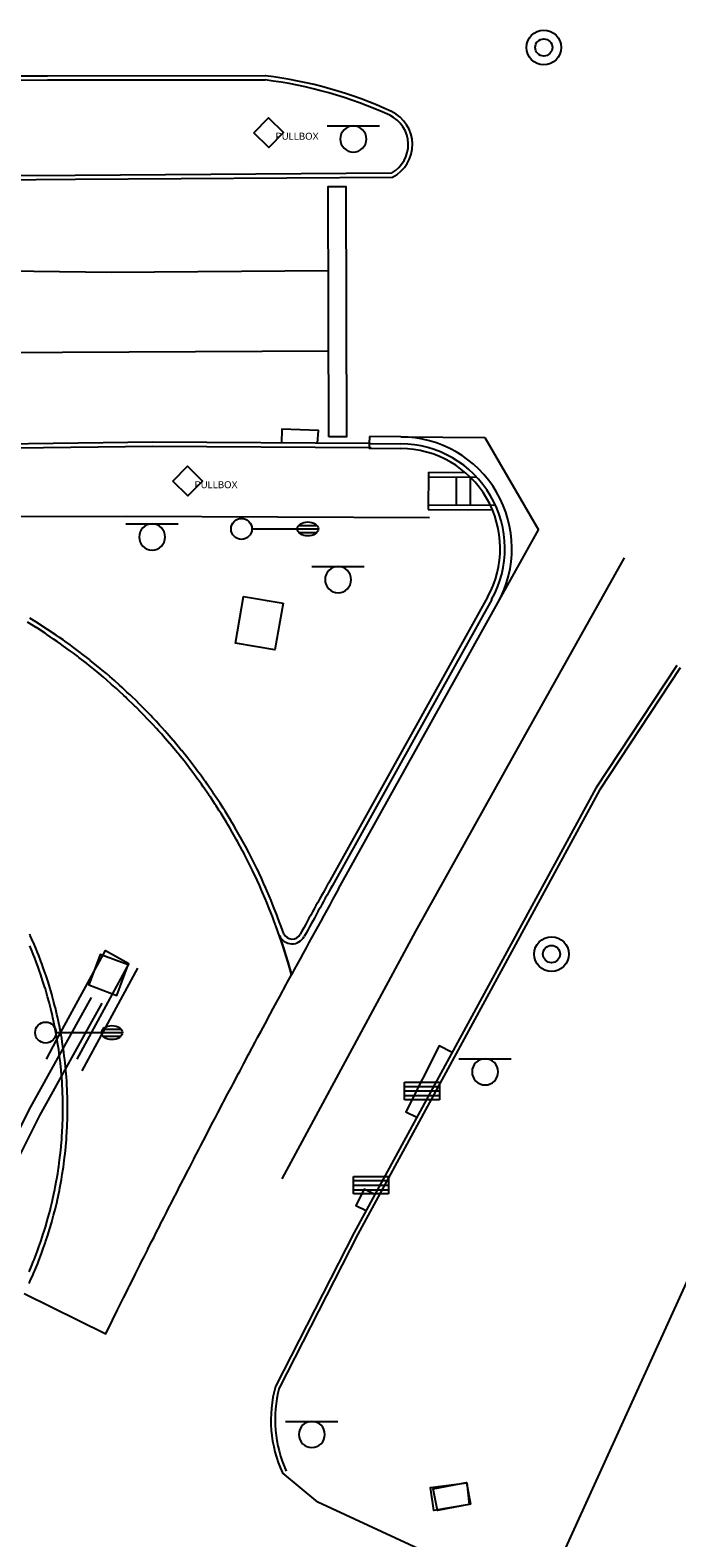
# Model space of a CAD drawing. Extents: x 2145380 to 2157287, y 139568 to 149130.
# Drawn here: x 2151198.1 to 2151290.7, y 148084.3 to 148300.2 of the extents above; entities that cross this region are included whole.
import ezdxf

# ---------------------------------------------------------------- set-up
doc = ezdxf.new("R2010")
doc.units = 0
for name, color, linetype in [('Default', 7, 'Continuous'), ('PR_PREVIOUSLY CONSTRUCTED', 7, 'Continuous'), ('TOPO_Asphalt', 7, 'Continuous'), ('TOPO_Concrete', 7, 'Continuous'), ('TOPO_Curb Back', 7, 'Continuous'), ('TOPO_DRAIN_Inlet Grate', 7, 'Continuous'), ('TOPO_DRAIN_Inlet Top Grate', 7, 'Continuous'), ('TOPO_Flowline', 7, 'Continuous'), ('TOPO_Light Pole', 7, 'Continuous'), ('TOPO_Misc Line', 7, 'Continuous'), ('TOPO_Power Pullbox', 7, 'Continuous'), ('TOPO_San Manhole', 7, 'Continuous'), ('TOPO_Sidewalk', 7, 'Continuous'), ('TOPO_Sign', 7, 'Continuous'), ('TOPO_Wall Freestanding', 7, 'Continuous')]:
    doc.layers.add(name, color=color, linetype=linetype)

# ---------------------------------------------------------------- blocks, each defined once
blk = doc.blocks.new('LP')
at = {"layer": 'TOPO_Light Pole'}
blk.add_line((3.81, 0), (20.32, 0), dxfattribs=at)
for points in [[(20.32, 0), (27.94, 0)], [(20.32, 0), (23.5, 0)], [(20.83, 1.27), (27.43, 1.27)], [(20.83, 1.27), (23.5, 1.27)], [(23.71, 1.27), (27.43, 1.27)], [(23.71, 0), (27.94, 0)], [(20.83, -1.27), (27.43, -1.27)], [(20.83, -1.27), (23.5, -1.27)], [(23.71, -1.27), (27.43, -1.27)]]:
    blk.add_lwpolyline(points, dxfattribs=at)
blk.add_circle((0, 0), 3.81, dxfattribs=at)
blk.add_ellipse((24.13, 0), major_axis=(3.81, 0), ratio=0.666667, dxfattribs=at)
blk = doc.blocks.new('pulbox')
at = {"layer": 'Default'}
blk.add_lwpolyline([(-5.38, -0.01), (-0.02, 5.42), (5.4, 0.06), (0.05, -5.36), (-5.38, -0.01)], dxfattribs=at)
blk.add_text('PULLBOX', height=2.54, dxfattribs=at).set_placement((2.54, -2.54))
blk = doc.blocks.new('EXMHSS')
at = {"layer": 'Default'}
for radius in [6.3, 3.13]:
    blk.add_circle((0, 0), radius, dxfattribs=at)
blk = doc.blocks.new('INLET')
at = {"layer": 'Default'}
for p, q in [((-6.35, 0), (-6.35, 6.35)), ((-6.35, 6.35), (6.35, 6.35)), ((6.35, 6.35), (6.35, 0)), ((-6.35, 4.82), (6.35, 4.82)), ((-6.35, 3.18), (6.35, 3.18)), ((-6.35, 1.47), (6.35, 1.47)), ((6.35, 0), (-6.35, 0))]:
    blk.add_line(p, q, dxfattribs=at)

msp = doc.modelspace()

# ---------------------------------------------------------------- linework, layer by layer
at = {"layer": 'PR_PREVIOUSLY CONSTRUCTED'}
for p, q in [((2151246.7, 148242.01), (2151246.69, 148241.01)), ((2151246.69, 148241.01), (2151251.2, 148240.98)), ((2151251.21, 148241.98), (2151246.7, 148242.01)), ((2151263.21, 148241.9), (2151270.92, 148228.68)), ((2151255.15, 148236.91), (2151255.11, 148231.58)), ((2151255.14, 148236.25), (2151262.08, 148236.2)), ((2151255.15, 148236.91), (2151260.41, 148236.88)), ((2151259.14, 148236.22), (2151259.12, 148232.22)), ((2151261.14, 148236.21), (2151261.12, 148232.21)), ((2151255.12, 148232.25), (2151264.76, 148232.18)), ((2151255.11, 148231.58), (2151264.32, 148231.52)), ((2151263.63, 148219.01), (2151240.83, 148178.05)), ((2151264.21, 148218.68), (2151241.41, 148177.72)), ((2151242.29, 148177.26), (2151265.08, 148218.2))]:
    msp.add_line(p, q, dxfattribs=at)
for points in [[(2151246.69, 148241.01), (2151246.68, 148240.34), (2151251.2, 148240.31)], [(2151251.21, 148241.98), (2151263.21, 148241.9)], [(2151265.08, 148218.2), (2151270.92, 148228.68)], [(2151197.29, 148119.31), (2151208.95, 148113.55), (2151209.49, 148114.64), (2151209.8, 148115.26), (2151210.03, 148115.73), (2151210.57, 148116.83), (2151210.64, 148116.97), (2151211.11, 148117.92), (2151211.49, 148118.68), (2151211.66, 148119.02), (2151212.21, 148120.12), (2151212.35, 148120.4), (2151212.76, 148121.22), (2151213.21, 148122.13), (2151213.31, 148122.33), (2151213.87, 148123.44), (2151214.08, 148123.87), (2151214.43, 148124.55), (2151214.96, 148125.62), (2151214.99, 148125.68), (2151215.56, 148126.81), (2151215.86, 148127.39), (2151216.14, 148127.94), (2151216.72, 148129.09), (2151216.76, 148129.18), (2151217.31, 148130.25), (2151217.69, 148130.99), (2151217.9, 148131.41), (2151218.5, 148132.59), (2151218.62, 148132.83), (2151219.11, 148133.78), (2151219.58, 148134.7), (2151219.72, 148134.98), (2151220.35, 148136.19), (2151220.56, 148136.61), (2151220.98, 148137.42), (2151221.56, 148138.54), (2151221.62, 148138.67), (2151222.28, 148139.93), (2151222.58, 148140.52), (2151222.94, 148141.21), (2151223.61, 148142.51), (2151223.63, 148142.55), (2151224.3, 148143.83), (2151224.72, 148144.62), (2151225, 148145.17), (2151225.72, 148146.54), (2151225.83, 148146.75), (2151226.45, 148147.93), (2151226.98, 148148.95), (2151227.19, 148149.34), (2151227.95, 148150.79), (2151228.18, 148151.2), (2151228.73, 148152.26), (2151229.41, 148153.53), (2151229.53, 148153.76), (2151230.35, 148155.3), (2151230.7, 148155.95), (2151231.19, 148156.87), (2151232.04, 148158.45), (2151232.06, 148158.48), (2151232.94, 148160.14), (2151233.44, 148161.05), (2151233.86, 148161.83), (2151234.8, 148163.57), (2151234.9, 148163.76), (2151235.53, 148164.93), (2151235.53, 148164.93), (2151235.52, 148164.95), (2151235.43, 148165.3), (2151235.15, 148166.31), (2151235, 148166.81), (2151234.55, 148168.31), (2151234.44, 148168.66), (2151234.07, 148169.8), (2151233.66, 148170.98), (2151233.56, 148171.28), (2151233.02, 148172.74), (2151232.82, 148173.28), (2151232.46, 148174.2), (2151231.92, 148175.54), (2151231.87, 148175.64), (2151231.26, 148177.08), (2151230.95, 148177.78), (2151230.62, 148178.5), (2151229.96, 148179.9), (2151229.92, 148179.98), (2151229.27, 148181.29), (2151228.83, 148182.15), (2151228.56, 148182.67), (2151228.54, 148182.71), (2151227.82, 148184.03), (2151227.68, 148184.28), (2151227.64, 148184.35), (2151227.06, 148185.38), (2151226.71, 148185.97), (2151226.47, 148186.38), (2151226.27, 148186.71), (2151225.75, 148187.57), (2151225.47, 148188.03), (2151225.21, 148188.43), (2151224.75, 148189.14), (2151224.64, 148189.32), (2151223.89, 148190.45), (2151223.78, 148190.61), (2151223.73, 148190.69), (2151222.91, 148191.87), (2151222.66, 148192.22), (2151222.52, 148192.42), (2151222.01, 148193.12), (2151221.57, 148193.71), (2151221.1, 148194.35), (2151221.09, 148194.35), (2151220.45, 148195.19), (2151220.16, 148195.56), (2151219.62, 148196.24), (2151219.3, 148196.63), (2151219.2, 148196.75), (2151218.23, 148197.92), (2151218.12, 148198.05), (2151218.09, 148198.08), (2151217.23, 148199.07), (2151216.91, 148199.43), (2151216.52, 148199.87), (2151216.21, 148200.2), (2151215.67, 148200.79), (2151215.18, 148201.32), (2151214.9, 148201.61), (2151214.41, 148202.12), (2151214.13, 148202.41), (2151213.24, 148203.3), (2151213.12, 148203.42), (2151213.06, 148203.48), (2151211.97, 148204.53), (2151211.81, 148204.69), (2151211.54, 148204.94), (2151210.86, 148205.56), (2151210.47, 148205.93), (2151209.79, 148206.53), (2151209.74, 148206.57), (2151209.1, 148207.13), (2151208.61, 148207.56), (2151208.01, 148208.07), (2151207.72, 148208.31), (2151207.46, 148208.53), (2151206.31, 148209.45), (2151206.29, 148209.47), (2151206.19, 148209.55), (2151205.11, 148210.39), (2151204.88, 148210.56), (2151204.33, 148210.98), (2151203.91, 148211.29), (2151203.44, 148211.64), (2151202.71, 148212.16), (2151202.45, 148212.35), (2151201.97, 148212.68), (2151201.49, 148213.02), (2151200.53, 148213.66), (2151200.48, 148213.69), (2151200.25, 148213.85), (2151199.01, 148214.65), (2151198.98, 148214.67), (2151198.58, 148214.92), (2151197.75, 148215.44)], [(2151234.43, 148170.81), (2151234.29, 148171.2), (2151234.19, 148171.5), (2151233.65, 148172.98), (2151233.45, 148173.51), (2151233.08, 148174.45), (2151232.53, 148175.8), (2151232.49, 148175.9), (2151231.87, 148177.34), (2151231.56, 148178.05), (2151231.23, 148178.77), (2151230.56, 148180.19), (2151230.52, 148180.27), (2151229.87, 148181.59), (2151229.42, 148182.46), (2151229.15, 148182.98), (2151229.13, 148183.02), (2151228.4, 148184.35), (2151228.26, 148184.61), (2151228.22, 148184.68), (2151227.64, 148185.71), (2151227.29, 148186.31), (2151227.05, 148186.72), (2151226.85, 148187.05), (2151226.32, 148187.92), (2151226.03, 148188.38), (2151225.77, 148188.79), (2151225.31, 148189.51), (2151225.2, 148189.69), (2151224.44, 148190.82), (2151224.34, 148190.98), (2151224.28, 148191.07), (2151223.46, 148192.25), (2151223.21, 148192.6), (2151223.06, 148192.81), (2151222.55, 148193.51), (2151222.11, 148194.11), (2151221.63, 148194.75), (2151221.62, 148194.76), (2151220.98, 148195.6), (2151220.69, 148195.97), (2151220.14, 148196.66), (2151219.82, 148197.05), (2151219.72, 148197.17), (2151218.73, 148198.35), (2151218.63, 148198.48), (2151218.6, 148198.51), (2151217.73, 148199.51), (2151217.41, 148199.88), (2151217.02, 148200.31), (2151216.71, 148200.66), (2151216.16, 148201.25), (2151215.66, 148201.78), (2151215.39, 148202.07), (2151214.89, 148202.59), (2151214.6, 148202.88), (2151213.71, 148203.77), (2151213.59, 148203.9), (2151213.52, 148203.96), (2151212.43, 148205.02), (2151212.26, 148205.17), (2151211.99, 148205.43), (2151211.32, 148206.06), (2151210.91, 148206.42), (2151210.24, 148207.03), (2151210.19, 148207.07), (2151209.54, 148207.64), (2151209.04, 148208.07), (2151208.44, 148208.58), (2151208.15, 148208.82), (2151207.88, 148209.04), (2151206.73, 148209.97), (2151206.71, 148209.99), (2151206.6, 148210.07), (2151205.52, 148210.92), (2151205.29, 148211.09), (2151204.73, 148211.51), (2151204.31, 148211.83), (2151203.83, 148212.18), (2151203.09, 148212.71), (2151202.83, 148212.89), (2151202.35, 148213.23), (2151201.86, 148213.57), (2151200.9, 148214.22), (2151200.85, 148214.25), (2151200.62, 148214.4), (2151199.36, 148215.22), (2151199.34, 148215.23), (2151198.93, 148215.49), (2151198.1, 148216.01)], [(2151197.96, 148120.72), (2151198.14, 148121.12), (2151198.55, 148122.03), (2151198.6, 148122.15), (2151198.93, 148122.95), (2151199.2, 148123.59), (2151199.31, 148123.88), (2151199.67, 148124.81), (2151199.76, 148125.05), (2151200.01, 148125.75), (2151200.28, 148126.53), (2151200.34, 148126.7), (2151200.65, 148127.65), (2151200.76, 148128.01), (2151200.94, 148128.6), (2151201.21, 148129.51), (2151201.22, 148129.56), (2151201.49, 148130.53), (2151201.62, 148131.02), (2151201.73, 148131.5), (2151201.97, 148132.47), (2151201.98, 148132.55), (2151202.18, 148133.45), (2151202.31, 148134.07), (2151202.38, 148134.43), (2151202.56, 148135.41), (2151202.6, 148135.61), (2151202.73, 148136.39), (2151202.84, 148137.16), (2151202.88, 148137.38), (2151203.01, 148138.37), (2151203.05, 148138.71), (2151203.13, 148139.37), (2151203.22, 148140.26), (2151203.23, 148140.36), (2151203.31, 148141.36), (2151203.34, 148141.82), (2151203.37, 148142.36), (2151203.42, 148143.36), (2151203.43, 148143.38), (2151203.46, 148144.36), (2151203.47, 148144.95), (2151203.47, 148145.35), (2151203.47, 148146.35), (2151203.47, 148146.51), (2151203.46, 148147.35), (2151203.44, 148148.08), (2151203.42, 148148.35), (2151203.37, 148149.35), (2151203.36, 148149.64), (2151203.31, 148150.35), (2151203.24, 148151.2), (2151203.22, 148151.35), (2151203.12, 148152.34), (2151203.08, 148152.75), (2151203.01, 148153.34), (2151202.88, 148154.31), (2151202.87, 148154.33), (2151202.73, 148155.32), (2151202.64, 148155.85), (2151202.56, 148156.3), (2151202.38, 148157.28), (2151202.36, 148157.39), (2151202.23, 148158.03), (2151202.23, 148158.03), (2151202.23, 148158.04), (2151202.18, 148158.26), (2151202.04, 148158.92), (2151201.96, 148159.24), (2151201.73, 148160.21), (2151201.67, 148160.44), (2151201.48, 148161.18), (2151201.27, 148161.95), (2151201.22, 148162.15), (2151200.94, 148163.11), (2151200.84, 148163.46), (2151200.65, 148164.06), (2151200.36, 148164.95), (2151200.33, 148165.01), (2151200.01, 148165.96), (2151199.84, 148166.42), (2151199.66, 148166.9), (2151199.31, 148167.83), (2151199.28, 148167.88), (2151198.93, 148168.76), (2151198.69, 148169.33), (2151198.54, 148169.68), (2151198.53, 148169.71), (2151198.14, 148170.59), (2151198.06, 148170.76)], [(2151233.8, 148170.57), (2151234.07, 148169.8), (2151234.25, 148169.23), (2151234.44, 148168.66), (2151234.55, 148168.31), (2151234.78, 148167.56), (2151235, 148166.81), (2151235.29, 148165.8), (2151235.43, 148165.3), (2151235.53, 148164.93)], [(2151197.98, 148122.41), (2151198.32, 148123.21), (2151198.57, 148123.84), (2151198.69, 148124.12), (2151199.04, 148125.05), (2151199.13, 148125.28), (2151199.38, 148125.98), (2151199.65, 148126.74), (2151199.7, 148126.91), (2151200.01, 148127.85), (2151200.12, 148128.21), (2151200.3, 148128.79), (2151200.57, 148129.7), (2151200.58, 148129.74), (2151200.84, 148130.7), (2151200.97, 148131.19), (2151201.08, 148131.66), (2151201.31, 148132.62), (2151201.33, 148132.69), (2151201.52, 148133.58), (2151201.65, 148134.21), (2151201.72, 148134.55), (2151201.9, 148135.52), (2151201.94, 148135.73), (2151202.07, 148136.5), (2151202.18, 148137.25), (2151202.21, 148137.48), (2151202.34, 148138.46), (2151202.38, 148138.79), (2151202.46, 148139.44), (2151202.55, 148140.33), (2151202.56, 148140.42), (2151202.64, 148141.41), (2151202.67, 148141.87), (2151202.71, 148142.4), (2151202.76, 148143.38), (2151202.76, 148143.41), (2151202.79, 148144.37), (2151202.8, 148144.96), (2151202.8, 148145.36), (2151202.8, 148146.35), (2151202.8, 148146.5), (2151202.79, 148147.34), (2151202.77, 148148.05), (2151202.76, 148148.33), (2151202.71, 148149.31), (2151202.69, 148149.6), (2151202.64, 148150.3), (2151202.57, 148151.14), (2151202.56, 148151.29), (2151202.46, 148152.27), (2151202.41, 148152.68), (2151202.34, 148153.25), (2151202.21, 148154.21), (2151202.21, 148154.23), (2151202.06, 148155.21), (2151201.98, 148155.74), (2151201.9, 148156.18), (2151201.72, 148157.16), (2151201.7, 148157.26), (2151201.57, 148157.89), (2151201.57, 148157.89), (2151201.57, 148157.9), (2151201.52, 148158.13), (2151201.38, 148158.77), (2151201.31, 148159.09), (2151201.08, 148160.05), (2151201.03, 148160.28), (2151200.84, 148161.01), (2151200.63, 148161.78), (2151200.58, 148161.97), (2151200.3, 148162.92), (2151200.19, 148163.26), (2151200.01, 148163.86), (2151199.72, 148164.73), (2151199.7, 148164.8), (2151199.38, 148165.73), (2151199.21, 148166.19), (2151199.04, 148166.66), (2151198.68, 148167.59), (2151198.66, 148167.64), (2151198.31, 148168.5), (2151198.07, 148169.07)]]:
    msp.add_lwpolyline(points, dxfattribs=at)
for centre, radius, start, end in [((2151251.1, 148225.98), 15, 330.8964, 89.6352), ((2151251.1, 148225.98), 16, 330.8964, 89.6352), ((2151251.1, 148225.98), 14.33, 330.8964, 89.6352), ((2152504.96, 147475.65), 1446.17, 150.94229, 151.27221), ((2152506.01, 147475.92), 1445.29, 150.97058, 151.52808), ((2152504.96, 147475.65), 1445.51, 150.94229, 151.27221), ((2151235.63, 148171.39), 2, 204.1556, 331.2722), ((2151235.63, 148171.39), 1.33, 205.7085, 331.2722)]:
    msp.add_arc(centre, radius, start, end, dxfattribs=at)
at = {"layer": 'TOPO_Asphalt'}
for points in [[(2151293.77, 148124.59), (2151273.78, 148080.68)], [(2151266.81, 148076.66), (2151239.33, 148089.45), (2151234.24, 148093.63)]]:
    msp.add_lwpolyline(points, dxfattribs=at)
at = {"layer": 'TOPO_Concrete'}
for points in [[(2151234.33, 148218.15), (2151233.18, 148211.46), (2151227.53, 148212.43), (2151228.68, 148219.12), (2151234.33, 148218.15)], [(2151200.47, 148152.87), (2151201.88, 148155.6), (2151208.91, 148168.4), (2151212.27, 148166.57)], [(2151212.16, 148166.36), (2151208.17, 148167.86), (2151206.53, 148163.49), (2151210.52, 148161.99), (2151212.16, 148166.36)]]:
    msp.add_lwpolyline(points, dxfattribs=at)
at = {"layer": 'TOPO_Curb Back'}
for points in [[(2151231.8, 148293.07), (2151200.63, 148293.04), (2151192.16, 148293)], [(2151231.8, 148293.67), (2151200.63, 148293.64), (2151192.34, 148293.6)], [(2151187.92, 148279.35), (2151204.59, 148279.46), (2151249.88, 148279.76)], [(2151187.74, 148278.75), (2151204.6, 148278.86), (2151250.03, 148279.16)], [(2151246.66, 148240.41), (2151215.7, 148240.6), (2151176.47, 148240.1), (2151175.75, 148240.1)], [(2151246.69, 148241.01), (2151215.7, 148241.2), (2151176.46, 148240.7), (2151175.94, 148240.7)], [(2151290.73, 148209.24), (2151279.13, 148191.68), (2151244.52, 148128.06), (2151233.24, 148105.99)], [(2151291.21, 148208.88), (2151279.64, 148191.37), (2151245.05, 148127.78), (2151233.8, 148105.77)]]:
    msp.add_lwpolyline(points, dxfattribs=at)
for centre, radius, start, end in [((2151224.4, 148232.85), 60.67, 65.4432, 83.0361), ((2151224.4, 148232.85), 61.27, 65.4398, 83.036), ((2151247.62, 148283.82), 4.65, 299.0068, 64.6409), ((2151247.62, 148283.82), 5.25, 297.2882, 64.6888), ((2151245.75, 148229.96), 10.49, 83.4979, 85.0203), ((2151245.75, 148229.96), 11.09, 84.2008, 85.1469), ((2151250.74, 148101.2), 18.15, 164.6792, 204.6331), ((2151250.74, 148101.2), 17.55, 164.8784, 204.6334)]:
    msp.add_arc(centre, radius, start, end, dxfattribs=at)
at = {"layer": 'TOPO_DRAIN_Inlet Grate'}
for points in [[(2151239.27, 148241.05), (2151239.4, 148242.89), (2151234.14, 148243.06), (2151234.13, 148241.09)], [(2151258.54, 148153.83), (2151256.71, 148154.75), (2151251.94, 148145.32), (2151253.49, 148144.54)], [(2151247.46, 148133.46), (2151245.94, 148134.23), (2151244.78, 148131.93), (2151246.23, 148131.19)]]:
    msp.add_lwpolyline(points, dxfattribs=at)
msp.add_lwpolyline([(2151261.2, 148089.12), (2151256.43, 148088.22), (2151255.84, 148091.33), (2151260.61, 148092.24)], close=True, dxfattribs=at)
at = {"layer": 'TOPO_DRAIN_Inlet Top Grate'}
msp.add_lwpolyline([(2151260.67, 148092.2), (2151260.99, 148089.07), (2151255.94, 148088.24), (2151255.46, 148091.54), (2151260.67, 148092.2)], dxfattribs=at)
at = {"layer": 'TOPO_Flowline'}
for points in [[(2151128.18, 147986.85), (2151143.66, 148026.28), (2151161.77, 148069.04), (2151173.07, 148094.36), (2151186.76, 148123.15), (2151192.33, 148134.31), (2151197.99, 148145.6), (2151206.91, 148161.69)], [(2151129.78, 147986.22), (2151145.25, 148025.63), (2151163.36, 148068.35), (2151174.64, 148093.63), (2151188.31, 148122.4), (2151193.88, 148133.54), (2151199.51, 148144.8), (2151208.42, 148160.86)]]:
    msp.add_lwpolyline(points, dxfattribs=at)
at = {"layer": 'TOPO_Misc Line'}
msp.add_line((2151240.86, 148254.23), (2151180.18, 148253.97), dxfattribs=at)
msp.add_lwpolyline([(2151240.89, 148241.98), (2151240.81, 148277.82), (2151243.32, 148277.83), (2151243.4, 148241.99)], close=True, dxfattribs=at)
for points in [[(2151240.8, 148265.73), (2151209.73, 148265.53), (2151183.84, 148265.82)], [(2151283.19, 148224.65), (2151268.78, 148198.93), (2151253.3, 148171.18), (2151234.16, 148135.73)]]:
    msp.add_lwpolyline(points, dxfattribs=at)
at = {"layer": 'TOPO_Sidewalk'}
msp.add_lwpolyline([(2151175.29, 148230.53), (2151211.86, 148230.61), (2151255.32, 148230.43)], dxfattribs=at)
at = {"layer": 'TOPO_Sign'}
for points in [[(2151240.65, 148286.49), (2151248.14, 148286.5)], [(2151244.4, 148286.49), (2151244.4, 148286.49)], [(2151242.53, 148284.62), (2151242.53, 148284.62)], [(2151246.27, 148284.62), (2151246.27, 148284.62)], [(2151244.4, 148282.76), (2151244.4, 148282.76)], [(2151211.84, 148229.5), (2151219.33, 148229.51)], [(2151213.72, 148227.63), (2151213.72, 148227.63)], [(2151215.59, 148229.5), (2151215.59, 148229.5)], [(2151217.45, 148227.63), (2151217.45, 148227.63)], [(2151215.59, 148225.76), (2151215.59, 148225.76)], [(2151238.47, 148223.39), (2151245.97, 148223.39)], [(2151242.22, 148223.38), (2151242.22, 148223.38)], [(2151240.35, 148221.52), (2151240.35, 148221.52)], [(2151244.09, 148221.52), (2151244.09, 148221.52)], [(2151242.22, 148219.65), (2151242.22, 148219.65)], [(2151259.52, 148152.91), (2151267.02, 148152.92)], [(2151263.27, 148152.91), (2151263.27, 148152.91)], [(2151261.4, 148151.04), (2151261.4, 148151.04)], [(2151265.14, 148151.04), (2151265.14, 148151.04)], [(2151263.27, 148149.18), (2151263.27, 148149.18)], [(2151234.71, 148100.99), (2151242.2, 148100.99)], [(2151238.46, 148100.99), (2151238.46, 148100.99)], [(2151236.59, 148099.12), (2151236.59, 148099.12)], [(2151240.33, 148099.12), (2151240.33, 148099.12)], [(2151238.46, 148097.25), (2151238.46, 148097.25)]]:
    msp.add_lwpolyline(points, dxfattribs=at)
for centre, start, end in [((2151244.4, 148284.62), 90, 180), ((2151244.4, 148284.62), 360, 90), ((2151244.4, 148284.62), 180, 270), ((2151244.4, 148284.62), 270, 0), ((2151215.59, 148227.63), 90, 180), ((2151215.59, 148227.63), 180, 270), ((2151215.59, 148227.63), 360, 90), ((2151215.59, 148227.63), 270, 0), ((2151242.22, 148221.52), 90, 180), ((2151242.22, 148221.52), 360, 90), ((2151242.22, 148221.52), 180, 270), ((2151242.22, 148221.52), 270, 0), ((2151263.27, 148151.04), 90, 180), ((2151263.27, 148151.04), 360, 90), ((2151263.27, 148151.04), 180, 270), ((2151263.27, 148151.04), 270, 0), ((2151238.46, 148099.12), 90, 180), ((2151238.46, 148099.12), 360, 90), ((2151238.46, 148099.12), 180, 270), ((2151238.46, 148099.12), 270, 0)]:
    msp.add_arc(centre, 1.87, start, end, dxfattribs=at)
at = {"layer": 'TOPO_Wall Freestanding'}
for points in [[(2151212.27, 148166.57), (2151204.83, 148152.84)], [(2151213.51, 148165.9), (2151205.53, 148151.19)]]:
    msp.add_lwpolyline(points, dxfattribs=at)

# ---------------------------------------------------------------- block references
at = {"layer": 'TOPO_DRAIN_Inlet Top Grate', "xscale": 0.39370000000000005, "yscale": 0.3937000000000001}
for p in [(2151254.23, 148147.06), (2151246.93, 148133.57)]:
    msp.add_blockref('INLET', p, dxfattribs=at)
at = {"layer": 'TOPO_Light Pole', "xscale": 0.39370000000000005, "yscale": 0.3937000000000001}
for p in [(2151228.39, 148228.79), (2151200.34, 148156.67)]:
    msp.add_blockref('LP', p, dxfattribs=at)
at = {"layer": 'TOPO_Power Pullbox', "xscale": 0.39370000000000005, "yscale": 0.3937000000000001}
for p in [(2151232.27, 148285.52), (2151220.67, 148235.62)]:
    msp.add_blockref('pulbox', p, dxfattribs=at)
at = {"layer": 'TOPO_San Manhole', "xscale": 0.39370000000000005, "yscale": 0.3937000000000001}
for p in [(2151271.67, 148297.73), (2151272.78, 148167.91)]:
    msp.add_blockref('EXMHSS', p, dxfattribs=at)

doc.saveas('drawing.dxf')
